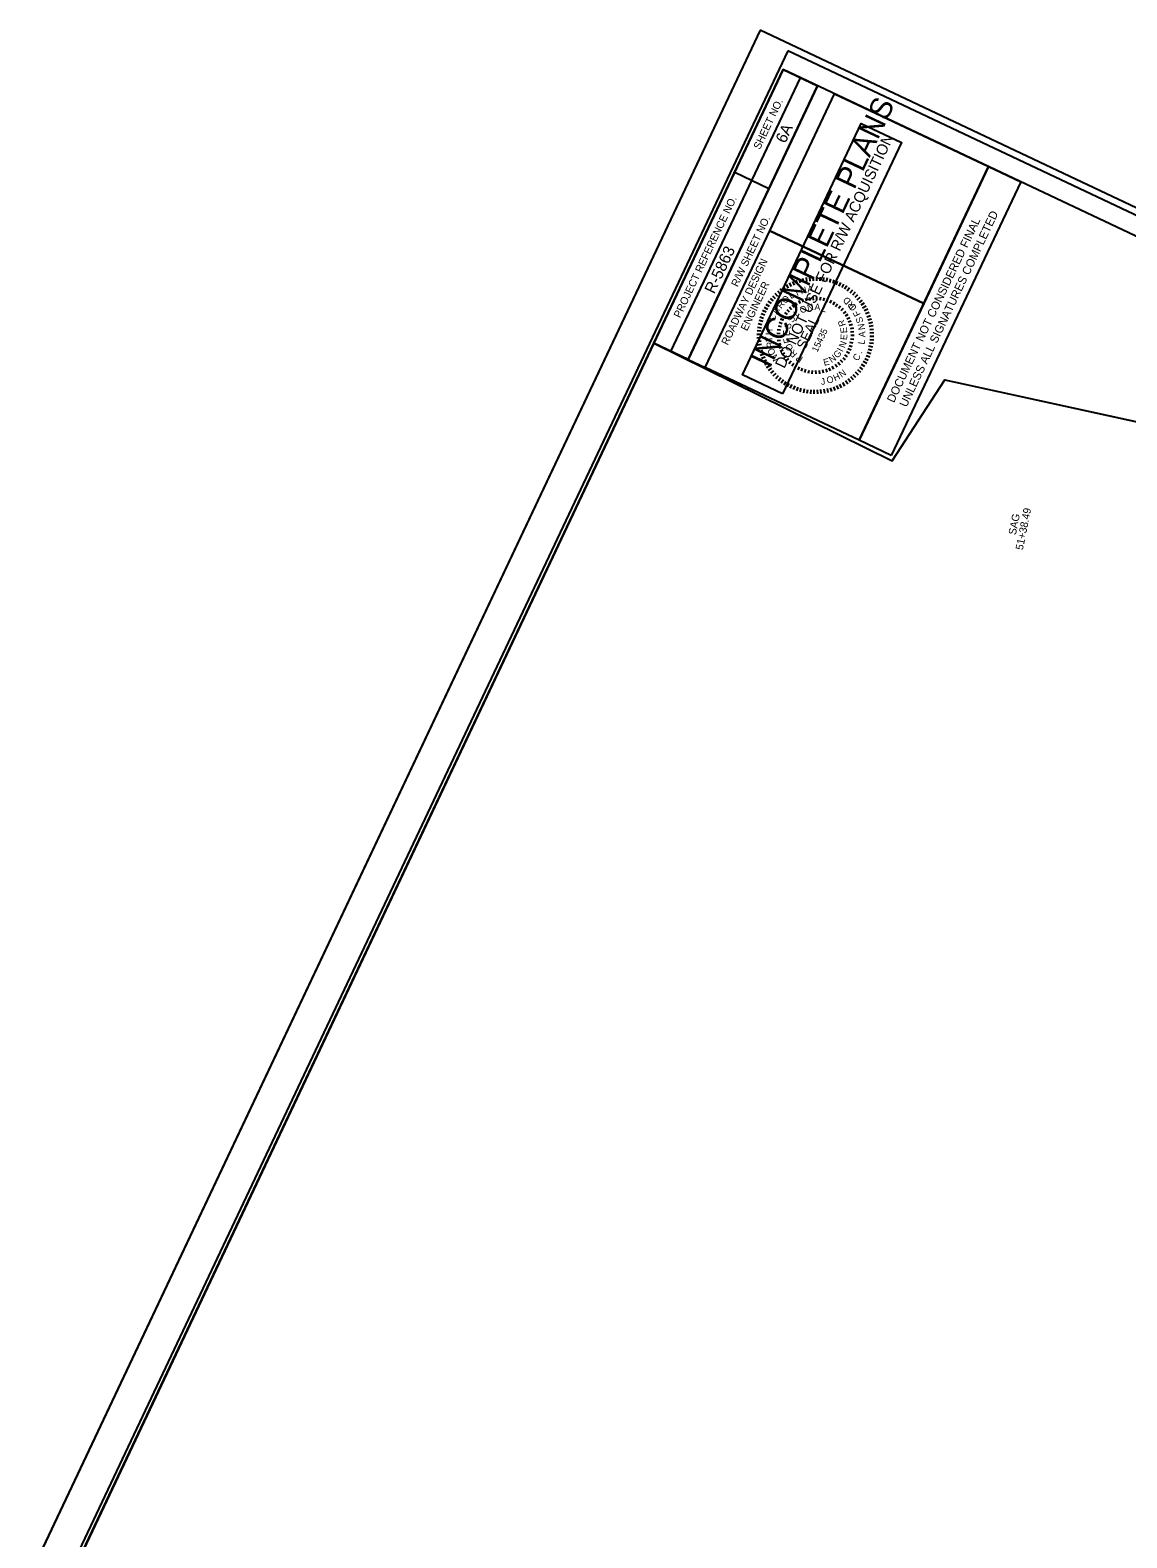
# Model space of a CAD drawing. Extents: x 555566 to 557881, y 503985 to 506091.
# Drawn here: x 556404 to 557129, y 505095 to 506091 of the extents above; entities that cross this region are included whole.
import ezdxf

# ---------------------------------------------------------------- set-up
doc = ezdxf.new("R2010")
doc.units = 0
for name, color, linetype in [('CTL Secondary Horizontal and Vertical CELL', 7, 'Continuous'), ('CTL Secondary Horizontal and Vertical Cogo Number', 7, 'Continuous'), ('Exist Building', 7, 'Continuous'), ('Exist Building Cogo Number', 7, 'Continuous'), ('Exist Building Cogo Point CELL', 7, 'Continuous'), ('Exist Hydro Jurisdictional Stream or Body of Water', 7, 'Continuous'), ('Exist Roads Curbs', 7, 'Continuous'), ('Exist Roads EOT', 7, 'Continuous'), ('Exist Structure Minor Head and End Wall', 7, 'Continuous'), ('Exist Utilities Telephone Pedestal CELL', 7, 'Continuous'), ('Exist Vegetation Tree CELL', 7, 'Continuous')]:
    doc.layers.add(name, color=color, linetype=linetype)

msp = doc.modelspace()

# ---------------------------------------------------------------- linework, layer by layer
at = {"layer": 'CTL Secondary Horizontal and Vertical CELL'}
for p, q in [((556827.79, 505878.96), (556913.28, 506059.82)), ((556839.1, 505873.62), (556924.58, 506054.48)), ((556839.1, 505873.62), (556924.58, 506054.48)), ((556869.93, 505997.36), (556892.53, 505986.68)), ((556893.15, 505958.73), (556994.82, 505910.68)), ((556839.1, 505873.62), (556850.4, 505868.28))]:
    msp.add_line(p, q, dxfattribs=at)
for points in [[(556901.93, 506065.19), (556260.95, 504709.04), (557210.25, 504260.35), (557851.24, 505616.5)], [(556816.45, 505884.32), (556901.93, 506065.19), (556924.58, 506054.48), (556839.1, 505873.62)], [(556893.15, 505958.73), (556935.88, 506049.14), (557037.59, 506001.07), (556994.86, 505910.66)], [(556850.4, 505868.28), (556893.15, 505958.73), (556994.86, 505910.66), (556952.11, 505820.2)]]:
    msp.add_lwpolyline(points, close=True, dxfattribs=at)
at = {"layer": 'Exist Building'}
msp.add_line((556886.6, 506091.24), (556166.98, 504568.74), dxfattribs=at)
at = {"layer": 'Exist Building Cogo Number'}
msp.add_lwpolyline([(556886.6, 506091.24), (556166.98, 504568.74), (557161.49, 504098.68), (557881.1, 505621.18)], close=True, dxfattribs=at)
at = {"layer": 'Exist Building Cogo Point CELL'}
msp.add_lwpolyline([(556904.97, 506077.58), (556192.83, 504570.9), (557146.75, 504120.03), (557858.88, 505626.71)], close=True, dxfattribs=at)
at = {"layer": 'Exist Hydro Jurisdictional Stream or Body of Water'}
for p, q in [((556901.86, 505921.84), (556903.31, 505919.63)), ((556903.85, 505923.06), (556905.16, 505920.78)), ((556905.9, 505924.17), (556907.08, 505921.81)), ((556908.03, 505925.15), (556909.06, 505922.73)), ((556910.2, 505926), (556911.09, 505923.52)), ((556912.42, 505926.72), (556913.16, 505924.19)), ((556914.69, 505927.3), (556915.27, 505924.73)), ((556916.98, 505927.75), (556917.41, 505925.15)), ((556919.3, 505928.05), (556919.57, 505925.43)), ((556921.63, 505928.22), (556921.74, 505925.58)), ((556923.97, 505928.24), (556923.91, 505925.6)), ((556926.3, 505928.12), (556926.09, 505925.49)), ((556928.62, 505927.87), (556928.25, 505925.25)), ((556930.93, 505927.47), (556930.4, 505924.89)), ((556933.2, 505926.93), (556932.52, 505924.39)), ((556935.44, 505926.26), (556934.6, 505923.76)), ((556937.63, 505925.45), (556936.64, 505923.01)), ((556939.77, 505924.51), (556938.64, 505922.13)), ((556941.85, 505923.45), (556940.58, 505921.14)), ((556943.86, 505922.26), (556942.46, 505920.03)), ((556945.8, 505920.96), (556944.26, 505918.82)), ((556891.8, 505912.17), (556893.94, 505910.63)), ((556893.22, 505914.02), (556895.27, 505912.36)), ((556894.76, 505915.79), (556896.7, 505914)), ((556896.39, 505917.46), (556898.22, 505915.56)), ((556898.13, 505919.02), (556899.84, 505917.02)), ((556899.95, 505920.49), (556901.54, 505918.38)), ((556909.91, 505911.33), (556911.06, 505909.45)), ((556912.08, 505912.51), (556913.04, 505910.53)), ((556914.34, 505913.47), (556915.11, 505911.41)), ((556916.69, 505914.22), (556917.25, 505912.09)), ((556919.1, 505914.73), (556919.46, 505912.56)), ((556921.54, 505915.01), (556921.69, 505912.81)), ((556924.01, 505915.05), (556923.94, 505912.85)), ((556926.47, 505914.85), (556926.18, 505912.67)), ((556928.89, 505914.42), (556928.4, 505912.27)), ((556931.26, 505913.75), (556930.57, 505911.67)), ((556933.56, 505912.86), (556932.67, 505910.85)), ((556935.76, 505911.75), (556934.68, 505909.84)), ((556947.65, 505919.53), (556945.99, 505917.49)), ((556949.42, 505918), (556947.63, 505916.06)), ((556951.09, 505916.37), (556949.18, 505914.54)), ((556952.65, 505914.63), (556950.65, 505912.92)), ((556954.12, 505912.81), (556952.01, 505911.22)), ((556955.46, 505910.9), (556953.26, 505909.45)), ((556886.5, 505901.81), (556889, 505900.97)), ((556887.31, 505904), (556889.75, 505903.02)), ((556888.24, 505906.14), (556890.63, 505905.01)), ((556889.31, 505908.22), (556891.62, 505906.95)), ((556890.5, 505910.24), (556892.72, 505908.83)), ((556901.32, 505902.66), (556903.2, 505901.54)), ((556902.69, 505904.71), (556904.45, 505903.41)), ((556904.24, 505906.62), (556905.88, 505905.15)), ((556905.98, 505908.37), (556907.46, 505906.75)), ((556907.87, 505909.94), (556909.2, 505908.19)), ((556936.52, 505908.68), (556937.77, 505910.48)), ((556939.79, 505908.92), (556938.36, 505907.25)), ((556941.58, 505907.23), (556940, 505905.71)), ((556943.19, 505905.37), (556941.47, 505904.01)), ((556944.63, 505903.37), (556942.78, 505902.18)), ((556945.86, 505901.23), (556943.91, 505900.23)), ((556956.69, 505908.91), (556954.41, 505907.59)), ((556957.8, 505906.85), (556955.44, 505905.67)), ((556958.78, 505904.73), (556956.35, 505903.7)), ((556959.63, 505902.55), (556957.15, 505901.67)), ((556884.63, 505892.67), (556887.26, 505892.46)), ((556884.89, 505894.99), (556887.5, 505894.62)), ((556885.29, 505897.3), (556887.87, 505896.77)), ((556885.83, 505899.57), (556888.37, 505898.89)), ((556897.74, 505891), (556899.93, 505890.87)), ((556897.99, 505893.45), (556900.17, 505893.11)), ((556898.49, 505895.86), (556900.62, 505895.32)), ((556899.21, 505898.22), (556901.28, 505897.47)), ((556900.16, 505900.49), (556902.14, 505899.55)), ((556902.14, 505899.55), (556900.16, 505900.49)), ((556946.88, 505898.99), (556944.84, 505898.18)), ((556947.68, 505896.66), (556945.57, 505896.05)), ((556948.25, 505894.27), (556946.09, 505893.86)), ((556948.59, 505891.83), (556946.4, 505891.63)), ((556960.35, 505900.33), (556957.81, 505899.6)), ((556960.93, 505898.07), (556958.36, 505897.49)), ((556961.37, 505895.78), (556958.77, 505895.35)), ((556961.68, 505893.46), (556959.06, 505893.19)), ((556961.85, 505891.13), (556959.21, 505891.02)), ((556884.52, 505890.34), (556887.15, 505890.28)), ((556884.54, 505888), (556887.18, 505888.11)), ((556884.71, 505885.67), (556887.33, 505885.94)), ((556885.01, 505883.35), (556887.61, 505883.78)), ((556885.46, 505881.06), (556888.03, 505881.64)), ((556897.72, 505888.53), (556899.91, 505888.62)), ((556897.94, 505886.08), (556900.12, 505886.38)), ((556898.39, 505883.66), (556900.53, 505884.17)), ((556899.08, 505881.29), (556901.16, 505882.01)), ((556947.56, 505882.08), (556945.46, 505882.73)), ((556948.17, 505884.47), (556946.02, 505884.91)), ((556948.55, 505886.9), (556946.36, 505887.13)), ((556948.69, 505889.36), (556946.49, 505889.38)), ((556961.1, 505881.83), (556958.51, 505882.36)), ((556961.5, 505884.14), (556958.88, 505884.51)), ((556961.75, 505886.46), (556959.12, 505886.67)), ((556961.86, 505888.79), (556959.23, 505888.84)), ((556886.04, 505878.8), (556888.57, 505879.53)), ((556886.76, 505876.57), (556889.24, 505877.46)), ((556887.61, 505874.4), (556890.03, 505875.43)), ((556888.59, 505872.28), (556890.95, 505873.45)), ((556889.69, 505870.22), (556891.98, 505871.54)), ((556899.99, 505879.01), (556901.99, 505879.91)), ((556901.11, 505876.81), (556903.02, 505877.91)), ((556902.45, 505874.75), (556904.24, 505876.02)), ((556903.98, 505872.81), (556905.63, 505874.25)), ((556905.68, 505871.03), (556907.19, 505872.63)), ((556907.55, 505869.43), (556908.9, 505871.17)), ((556939.48, 505869.95), (556938.07, 505871.64)), ((556941.3, 505871.61), (556939.73, 505873.16)), ((556941.23, 505874.82), (556942.94, 505873.43)), ((556944.41, 505875.43), (556942.58, 505876.64)), ((556945.67, 505877.54), (556943.74, 505878.57)), ((556946.73, 505879.76), (556944.7, 505880.61)), ((556957.08, 505870.91), (556954.77, 505872.18)), ((556958.14, 505872.99), (556955.76, 505874.12)), ((556959.08, 505875.13), (556956.64, 505876.11)), ((556959.88, 505877.32), (556957.39, 505878.16)), ((556960.56, 505879.56), (556958.01, 505880.24)), ((556890.92, 505868.23), (556893.12, 505869.68)), ((556892.27, 505866.32), (556894.38, 505867.91)), ((556893.73, 505864.5), (556895.74, 505866.21)), ((556895.3, 505862.76), (556897.2, 505864.59)), ((556896.96, 505861.13), (556898.75, 505863.07)), ((556898.73, 505859.6), (556900.4, 505861.64)), ((556909.57, 505868.01), (556910.74, 505869.87)), ((556911.71, 505866.8), (556912.7, 505868.76)), ((556913.96, 505865.8), (556914.76, 505867.84)), ((556916.3, 505865.02), (556916.89, 505867.13)), ((556918.7, 505864.47), (556919.09, 505866.63)), ((556921.15, 505864.15), (556921.32, 505866.34)), ((556923.61, 505864.08), (556923.57, 505866.27)), ((556926.06, 505864.23), (556925.82, 505866.41)), ((556928.5, 505864.63), (556928.04, 505866.78)), ((556930.88, 505865.26), (556930.22, 505867.35)), ((556933.19, 505866.11), (556932.33, 505868.13)), ((556935.4, 505867.19), (556934.35, 505869.11)), ((556937.51, 505868.47), (556936.27, 505870.29)), ((556948.26, 505860.11), (556946.55, 505862.11)), ((556949.99, 505861.67), (556948.17, 505863.57)), ((556951.63, 505863.34), (556949.69, 505865.13)), ((556953.16, 505865.1), (556951.12, 505866.77)), ((556954.58, 505866.96), (556952.44, 505868.5)), ((556955.89, 505868.89), (556953.66, 505870.3)), ((556900.59, 505858.17), (556902.12, 505860.31)), ((556902.52, 505856.87), (556903.93, 505859.1)), ((556904.53, 505855.68), (556905.8, 505857.99)), ((556906.61, 505854.62), (556907.74, 505857)), ((556908.76, 505853.68), (556909.74, 505856.12)), ((556910.95, 505852.87), (556911.78, 505855.37)), ((556913.18, 505852.2), (556913.87, 505854.74)), ((556915.46, 505851.66), (556915.99, 505854.24)), ((556917.76, 505851.26), (556918.14, 505853.88)), ((556920.08, 505851.01), (556920.29, 505853.64)), ((556922.42, 505850.89), (556922.47, 505853.53)), ((556924.75, 505850.91), (556924.65, 505853.55)), ((556927.09, 505851.08), (556926.82, 505853.7)), ((556929.4, 505851.38), (556928.98, 505853.98)), ((556931.69, 505851.83), (556931.12, 505854.4)), ((556933.96, 505852.41), (556933.23, 505854.94)), ((556936.18, 505853.13), (556935.3, 505855.61)), ((556938.36, 505853.98), (556937.33, 505856.4)), ((556940.48, 505854.96), (556939.3, 505857.32)), ((556942.54, 505856.07), (556941.22, 505858.35)), ((556944.52, 505857.29), (556943.07, 505859.5)), ((556946.44, 505858.64), (556944.85, 505860.75))]:
    msp.add_line(p, q, dxfattribs=at)
at = {"layer": 'Exist Roads Curbs'}
msp.add_lwpolyline([(556901.55, 505850.92), (556874.99, 505863.48), (556953.52, 506029.6), (556980.07, 506017.05)], close=True, dxfattribs=at)
at = {"layer": 'Exist Structure Minor Head and End Wall'}
msp.add_lwpolyline([(557047.43, 504351.91), (557011.84, 504393.69), (556904.12, 504418.34), (556404.92, 505013.64), (556816.45, 505884.32), (556973.87, 505806.54), (557008.7, 505860.07), (557008.7, 505860.07), (557512.37, 505750.31), (557851.24, 505616.5), (557197.58, 504288.36)], close=True, dxfattribs=at)
at = {"layer": 'Exist Utilities Telephone Pedestal CELL'}
for p, q in [((556952.11, 505820.2), (557037.59, 506001.06)), ((557037.6, 506001.05), (557058.85, 505991.01)), ((557058.83, 505991.01), (556973.35, 505810.16)), ((556973.35, 505810.16), (556952.11, 505820.2))]:
    msp.add_line(p, q, dxfattribs=at)
at = {"layer": 'Exist Vegetation Tree CELL'}
msp.add_line((557008.7, 505860.07), (557512.37, 505750.31), dxfattribs=at)

# ---------------------------------------------------------------- texts
at = {"layer": 'CTL Secondary Horizontal and Vertical CELL'}
for s, height, p in [('SHEET NO.', 5, (556886.52, 506011.97)), ('PROJECT REFERENCE NO.', 5.0001, (556833.8, 505900.68)), ('R/W SHEET NO.', 5.0001, (556871.77, 505921.22)), ('ROADWAY DESIGN', 5.0001, (556865.29, 505882.7)), ('ENGINEER', 5, (556878.07, 505892.08))]:
    msp.add_text(s, height=height, rotation=64.7021, dxfattribs=at).set_placement(p)
at = {"layer": 'CTL Secondary Horizontal and Vertical Cogo Number'}
for s, p in [('6A', (556903.29, 506015.99)), ('R-5863', (556856.33, 505916.52))]:
    msp.add_text(s, height=7.5, rotation=64.7021, dxfattribs=at).set_placement(p)
at = {"layer": 'Exist Hydro Jurisdictional Stream or Body of Water'}
for s, height, rotation, p in [('N', 4.39, 14.90689, (556913.83, 505916.59)), ('A', 4.39, 5.13936, (556918, 505917.82)), ('R', 4.39, 49.96992, (556900.55, 505906.88)), ('O', 4.39, 46.9131, (556903.51, 505910.18)), ('L', 4.39, 33.77682, (556907.19, 505913.38)), ('I', 4.39, 24.20135, (556911.02, 505915.48)), ('N', 4.39, 11.0854, (556918.13, 505905.64)), (' RD', 4.391, 134.29468, (556951.1, 505908.22)), ('C', 4.39, 61.97922, (556895.83, 505898.65)), ('A', 4.39, 61.97922, (556897.97, 505902.95)), ('S', 4.39, 56.97414, (556908.1, 505897.57)), ('I', 4.39, 41.67789, (556910.96, 505901.38)), ('O', 4.39, 26.38164, (556914.02, 505903.84)), ('A', 4.39, 355.78915, (556922.41, 505906.27)), ('L', 4.39, 340.49291, (556926.95, 505905.7)), ('O ', 4.391, 125.62192, (556950.84, 505907.64)), ('F', 4.39, 116.82931, (556953.2, 505903.35)), ('S', 4.39, 107.94668, (556955, 505898.45)), ('H', 4.39, 85.68991, (556894.64, 505889.55)), ('E', 4.39, 87.56663, (556906.15, 505889.08)), ('S', 4.39, 72.27038, (556906.55, 505893.45)), ('SEAL', 6.591, 64.62226, (556916.34, 505879.74)), ('15435', 4.391, 64.62226, (556924.49, 505878.06)), ('R', 4.39, 109.18715, (556943.32, 505896.3)), ('E', 4.39, 95.41606, (556944.29, 505891.2)), ('N', 4.39, 99.06405, (556956, 505893.43)), ('A', 4.39, 90.24144, (556956.2, 505888.29)), ('T', 4.39, 95.12186, (556894.85, 505885.54)), ('R', 4.39, 103.28282, (556895.8, 505881.82)), ('O', 4.39, 116.33956, (556897.11, 505877.67)), ('F', 4.39, 102.86287, (556906.89, 505884.84)), ('O', 4.39, 118.15912, (556908.84, 505880.68)), ('I', 4.39, 62.40845, (556941.15, 505878.26)), ('N', 4.39, 70.03811, (556942.56, 505880.88)), ('E', 4.39, 85.43018, (556944.06, 505886.33)), ('L', 4.39, 81.23888, (556955.62, 505883.31)), ('N', 4.39, 118.29899, (556899.38, 505873.81)), ('R', 4.39, 133.45536, (556911.66, 505877.42)), ('P', 4.39, 148.75161, (556915.3, 505874.95)), ('E', 4.39, 14.69235, (556929.05, 505869.37)), ('N', 4.39, 35.54742, (556933.94, 505871.13)), ('G', 4.39, 44.31366, (556937.64, 505874.13)), ('C', 4.39, 60.71221, (556951.32, 505872.24)), ('.', 4.39, 68.45456, (556953.76, 505877.12)), ('J', 4.39, 8.55727, (556927.04, 505856.76)), ('O', 4.39, 16.62909, (556931.28, 505857.53)), ('H', 4.39, 25.27184, (556936.15, 505859.18)), ('N', 4.39, 33.94442, (556940.5, 505861.43))]:
    msp.add_text(s, height=height, rotation=rotation, dxfattribs=at).set_placement(p)
at = {"layer": 'Exist Roads Curbs'}
for s, height, p in [('INCOMPLETE PLANS', 14.4, (556893.1, 505867.31)), ('DO NOT USE FOR R/W ACQUISITION', 7.2, (556902.69, 505867.27))]:
    msp.add_text(s, height=height, rotation=64.7021, dxfattribs=at).set_placement(p)
at = {"layer": 'Exist Roads EOT'}
for s, p in [('SAG', (557055.55, 505757.4)), ('51+38.49', (557060.22, 505747.42))]:
    msp.add_text(s, height=5, rotation=78.58724, dxfattribs=at).set_placement(p)
at = {"layer": 'Exist Utilities Telephone Pedestal CELL'}
for s, p in [('UNLESS ALL SIGNATURES COMPLETED', (556983.43, 505841.66)), ('DOCUMENT NOT CONSIDERED FINAL', (556975.09, 505844.63))]:
    msp.add_text(s, height=5.5, rotation=64.7021, dxfattribs=at).set_placement(p)

doc.saveas('drawing.dxf')
